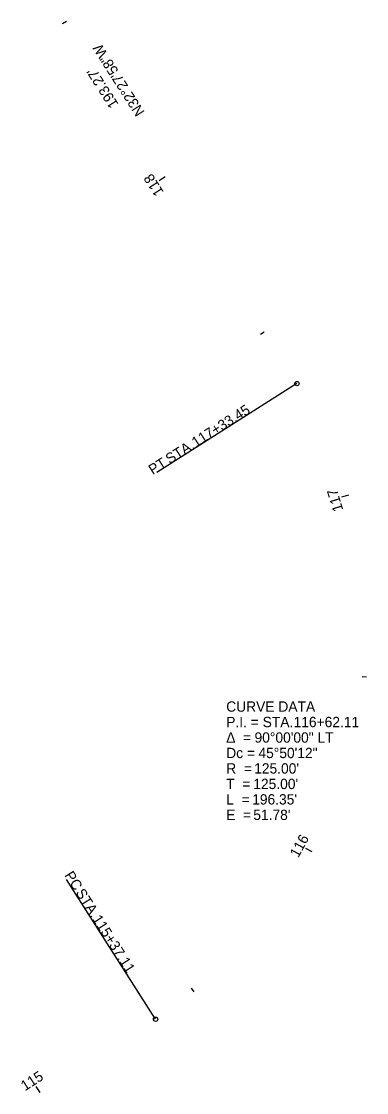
# Model space of a CAD drawing. Extents: x 143421 to 147121, y 511505 to 514560.
# Drawn here: x 145360.1 to 145453.7, y 512891.3 to 513182.1 of the extents above; entities that cross this region are included whole.
import ezdxf

# ---------------------------------------------------------------- set-up
doc = ezdxf.new("R2010")
doc.units = 0
for name, color, linetype in [('CM_Corridor_Top_Mesh', 7, 'Continuous'), ('DT_P_Tie', 7, 'Continuous'), ('DT_X_Triangles', 7, 'Continuous'), ('MD_P_Surface_Finished_Grade', 7, 'Continuous'), ('PF_X_Ground_Line', 7, 'Continuous')]:
    doc.layers.add(name, color=color, linetype=linetype)

msp = doc.modelspace()

# ---------------------------------------------------------------- linework, layer by layer
at = {"layer": 'DT_P_Tie'}
for p, q in [((145434.84, 513083.78), (145396.87, 513059.62)), ((145396.48, 512911.21), (145372.32, 512949.18))]:
    msp.add_line(p, q, dxfattribs=at)
for centre in [(145434.84, 513083.78), (145396.48, 512911.21)]:
    msp.add_circle(centre, 0.6, dxfattribs=at)
at = {"layer": 'DT_X_Triangles'}
for p, q in [((145372.28, 513182.11), (145371.27, 513181.46)), ((145399.12, 513139.92), (145397.43, 513138.85)), ((145425.96, 513097.74), (145424.95, 513097.09)), ((145448.83, 513053.5), (145446.92, 513052.91)), ((145453.74, 513004.07), (145452.55, 513004.19)), ((145439.02, 512956.64), (145437.26, 512957.6)), ((145406.98, 512918.68), (145406.24, 512919.62)), ((145365.17, 512891.3), (145364.1, 512892.98))]:
    msp.add_line(p, q, dxfattribs=at)

# ---------------------------------------------------------------- texts
at = {"layer": 'CM_Corridor_Top_Mesh'}
msp.add_text("193.27'", height=2.8, rotation=122.4662, dxfattribs=at).set_placement((145386.52, 513159.65))
at = {"layer": 'DT_P_Tie'}
for s, rotation, p in [('117+33.45', 32.4662, (145407.4, 513066.37)), (' STA. ', 32.4662, (145399.43, 513061.29)), ('PT', 32.4662, (145395.7, 513058.92)), ('PC', 302.4662, (145371.66, 512950.3)), (' STA. ', 302.4662, (145374.12, 512946.43)), ('115+37.11', 302.4662, (145379.2, 512938.45))]:
    msp.add_text(s, height=2.8, rotation=rotation, dxfattribs=at).set_placement(p)
at = {"layer": 'DT_X_Triangles'}
for s, rotation, p in [('118', 122.4662, (145398.8, 513135.77)), ('117', 107.1315, (145447.45, 513049.5)), ('116', 61.2949, (145435.21, 512954.89)), ('115', 32.4662, (145361.04, 512891.63))]:
    msp.add_text(s, height=2.8, rotation=rotation, dxfattribs=at).set_placement(p)
at = {"layer": 'MD_P_Surface_Finished_Grade'}
for s, p in [('CURVE DATA', (145415.66, 512994.7)), ('P.I. = STA. ', (145415.66, 512990.5)), ('116+62.11', (145433.93, 512990.5)), ('Δ  = ', (145415.66, 512986.3)), ('90°00\'00" LT', (145423.34, 512986.3)), ('Dc = ', (145415.66, 512982.1)), ('45°50\'12"', (145424.4, 512982.1)), ('R  = ', (145415.66, 512977.9)), ("125.00'", (145423.24, 512977.9)), ('T  = ', (145415.66, 512973.7)), ("125.00'", (145423, 512973.7)), ('L  = ', (145415.66, 512969.5)), ("196.35'", (145422.7, 512969.5)), ('E  = ', (145415.66, 512965.3)), ("51.78'", (145423, 512965.3))]:
    msp.add_text(s, height=2.8, dxfattribs=at).set_placement(p)
at = {"layer": 'PF_X_Ground_Line'}
msp.add_text('N32°27\'58"W', height=2.8, rotation=122.4662, dxfattribs=at).set_placement((145393.63, 513157.5))

doc.saveas('drawing.dxf')
